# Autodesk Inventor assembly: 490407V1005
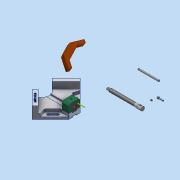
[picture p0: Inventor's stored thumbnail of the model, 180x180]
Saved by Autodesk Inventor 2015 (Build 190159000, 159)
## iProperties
Created: 2019-04
Part Number: 490407V1005
Document SubType Name: Assembly
Designer: SCD-A02
Author: SCD-A02
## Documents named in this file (11)
- C:\Users\SCD-A02\Desktop\490407V1005\490407V1005\490407V1005.iam
- C:\Users\SCD-A02\Desktop\490407V1005\본체.ipt
- C:\Users\SCD-A02\Desktop\490407V1005\490407V1005\리드스크류.ipt
- C:\Users\SCD-A02\Desktop\490407V1005\490407V1005\멈춤나사 M4x5.ipt
- C:\Users\SCD-A02\Desktop\490407V1005\490407V1005\멈춤나사 M4x10.ipt
- C:\Users\SCD-A02\Desktop\490407V1005\490407V1005\볼트 M4x16.ipt
- C:\Users\SCD-A02\Desktop\490407V1005\490407V1005\부시.ipt
- C:\Users\SCD-A02\Desktop\490407V1005\490407V1005\서포트.ipt
- C:\Users\SCD-A02\Desktop\490407V1005\490407V1005\조.ipt
- C:\Users\SCD-A02\Desktop\490407V1005\490407V1005\평행 핀 2.5x24.ipt
- C:\Users\SCD-A02\Desktop\490407V1005\490407V1005\핸들.ipt
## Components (1 placed, 1 different names)
1. 핸들:1
